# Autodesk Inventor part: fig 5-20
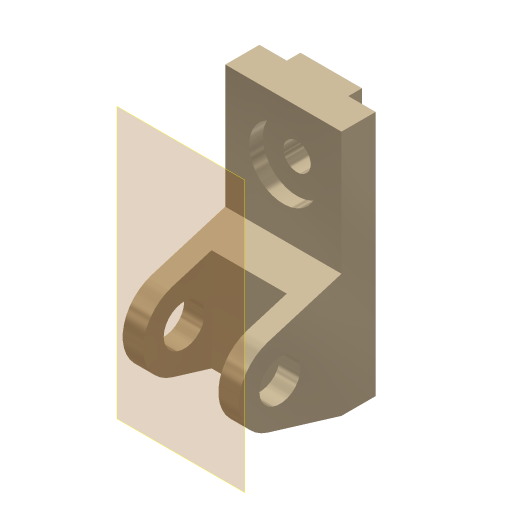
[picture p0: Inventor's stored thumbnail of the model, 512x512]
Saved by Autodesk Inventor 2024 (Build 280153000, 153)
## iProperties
Shininess: 65.0
Angle Display Precision: 2
Document Length Units: 11269
Document Angle Units: 11279
Document Time Units: 11290
Document Mass Units: 11283
Document Length Units Precision: 3
Document Angle Units Precision: 2
Compacted: False
Created: 2001-11
Part Number: fig 5-20
Document SubType Name: Modeling
Designer: Renu Muthoo
Density: 1 g/cm^3
Material: Generic
Appearance: Metal-Titanium (Polished)
Density: 0.0
Volumn: 0.0
Area: 0.0
PropertySet Name: Model Information
Control State: 0
Master: False
Checked Out: False
Author: Renu Muthoo
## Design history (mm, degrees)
sketch "Sketch2"
  geometry: L1 (33.257, 104.664)-(33.257, -75.336); L2 (33.257, -75.336)-(8.257, -75.336); L3 (8.257, -75.336)-(-45.451, -59.045); L4 (-45.451, -1.628)-(8.257, 14.664); L5 (8.257, 14.664)-(8.257, 104.664); L6 (8.257, 104.664)-(33.257, 104.664); C1 r 15 at (-36.743, -30.336); A1 r 30 centre (-36.743, -30.336) between (-45.451, -1.628) and (-45.451, -59.045)
  constraints: 12 end point, 2 centre point, 2 equal length, 2 parallel, 2 point on circle, 2 tangent, 1 coincident, 1 perpendicular, 1 vertical
  dimensions: "d0" = 180 distance of L1.start L1.end; "d1" = 30 radius of A1; "d2" = 25 distance of L5.end L1.start; "d3" = 45 distance from line of L2 A1.centre; "d4" = 70 distance from line of L1 A1.centre; "d5" = 30 diameter of C1
extrude "Extrusion1" new body sketch "Sketch2" distance "d6" = 85; taper "d7" = 0 deg
workplane "Work Plane1"
sketch "Sketch3"
  geometry: L1 (15, 62.364)-(70, 62.364); L2 (70, 62.364)-(70, -52.386); L3 (70, -52.386)-(15, -52.386); L4 (15, -52.386)-(15, 62.364); L5 (0, -45)-(0, -28.708) reference
  constraints: 8 end point, 2 parallel, 1 horizontal, 1 perpendicular
  dimensions: "d8" = 55 distance of L1.start L1.end; "d9" = 15 distance between parallel lines of L5 L4
extrude "Extrusion2" cut sketch "Sketch3" distance "d10" = 50; taper "d11" = 0 deg
sketch "Sketch4"
  geometry: L1 (0, 25)-(85, 25) reference; L2 (0, 0)-(0, 25) reference; L3 (20, 25)-(65, 25); L4 (65, 25)-(65, 35); L5 (65, 35)-(20, 35); L6 (20, 35)-(20, 25)
  constraints: 8 end point, 2 parallel, 1 horizontal, 1 perpendicular, 1 point on line
  dimensions: "d12" = 45 distance of L4.end L5.end; "d13" = 10 distance of L3.end L4.end; "d14" = 20 distance between parallel lines of L2 L6
extrude "Extrusion3" join sketch "Sketch4" stored distance "d15" = 50; taper "d16" = 0 deg
sketch "Sketch5"
  geometry: L1 (85, 0)-(85, 90) reference; L2 (0, 90)-(85, 90) reference; 1 further point
  dimensions: "d17" = 42 distance from line of L2 point (42.5, 48); "d18" = 42.5 distance from line of L1 point (42.5, 48)
hole "Hole1" sketch "Sketch5" diameter "d19" = 20; stored, may be unused: countersink angle "d23" = 82 deg, drill point angle "d25" = 118 deg; dims "d20" = 6, "d21" = 50, "d22" = 10, "d24" = 8
workplane "Work Plane10"
body "Solid1"
node "Sketch1"
